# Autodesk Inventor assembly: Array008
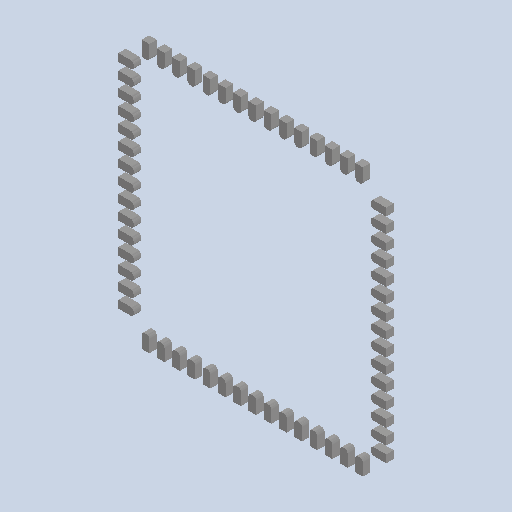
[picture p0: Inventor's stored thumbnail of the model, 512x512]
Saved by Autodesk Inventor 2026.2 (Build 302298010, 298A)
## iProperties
Created: 2026-10
Part Number: Array008
Document SubType Name: Assembly
Designer: mel
Author: mel
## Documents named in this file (5)
- D:\travail\année 2026-2027\1 sti2d IT\poubelle à verre\raspberry-pico-2-microcontroller-rp2350-1.snapshot.5\raspberry_pico_2\raspberry_pico_2\Array008.iam
- D:\travail\année 2026-2027\1 sti2d IT\poubelle à verre\raspberry-pico-2-microcontroller-rp2350-1.snapshot.5\raspberry_pico_2\raspberry_pico_2\Array004.iam
- D:\travail\année 2026-2027\1 sti2d IT\poubelle à verre\raspberry-pico-2-microcontroller-rp2350-1.snapshot.5\raspberry_pico_2\raspberry_pico_2\Array005.iam
- D:\travail\année 2026-2027\1 sti2d IT\poubelle à verre\raspberry-pico-2-microcontroller-rp2350-1.snapshot.5\raspberry_pico_2\raspberry_pico_2\Array006.iam
- D:\travail\année 2026-2027\1 sti2d IT\poubelle à verre\raspberry-pico-2-microcontroller-rp2350-1.snapshot.5\raspberry_pico_2\raspberry_pico_2\Array007.iam
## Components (4 placed, 4 different names)
1. 2705 [sub-assembly]
2. 2721 [sub-assembly]
3. 2737 [sub-assembly]
4. 2753 [sub-assembly]
